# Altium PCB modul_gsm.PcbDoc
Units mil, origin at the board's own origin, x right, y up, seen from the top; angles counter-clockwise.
Board outline 2825 x 1976 mil, 2 copper layers (Top Layer, Bottom Layer); 39 components, 43 nets, 183 pads, 157 vias.
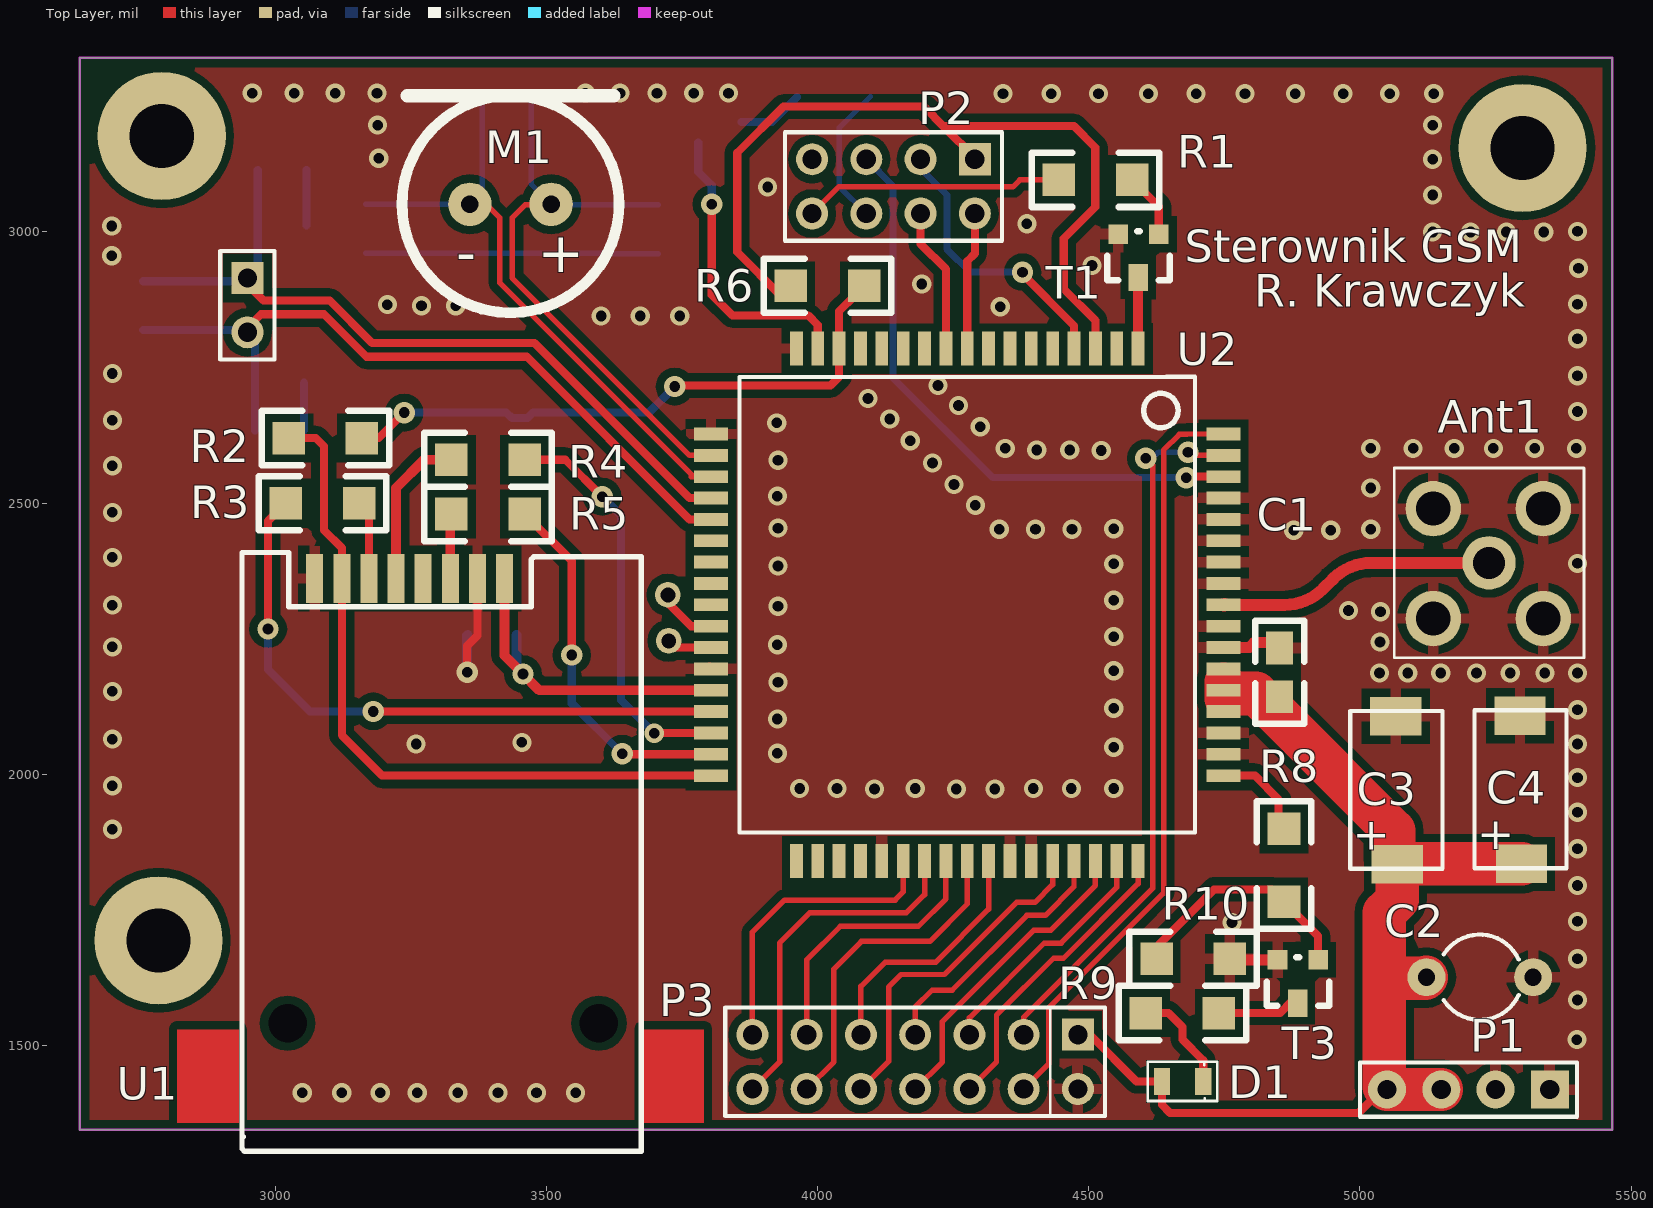
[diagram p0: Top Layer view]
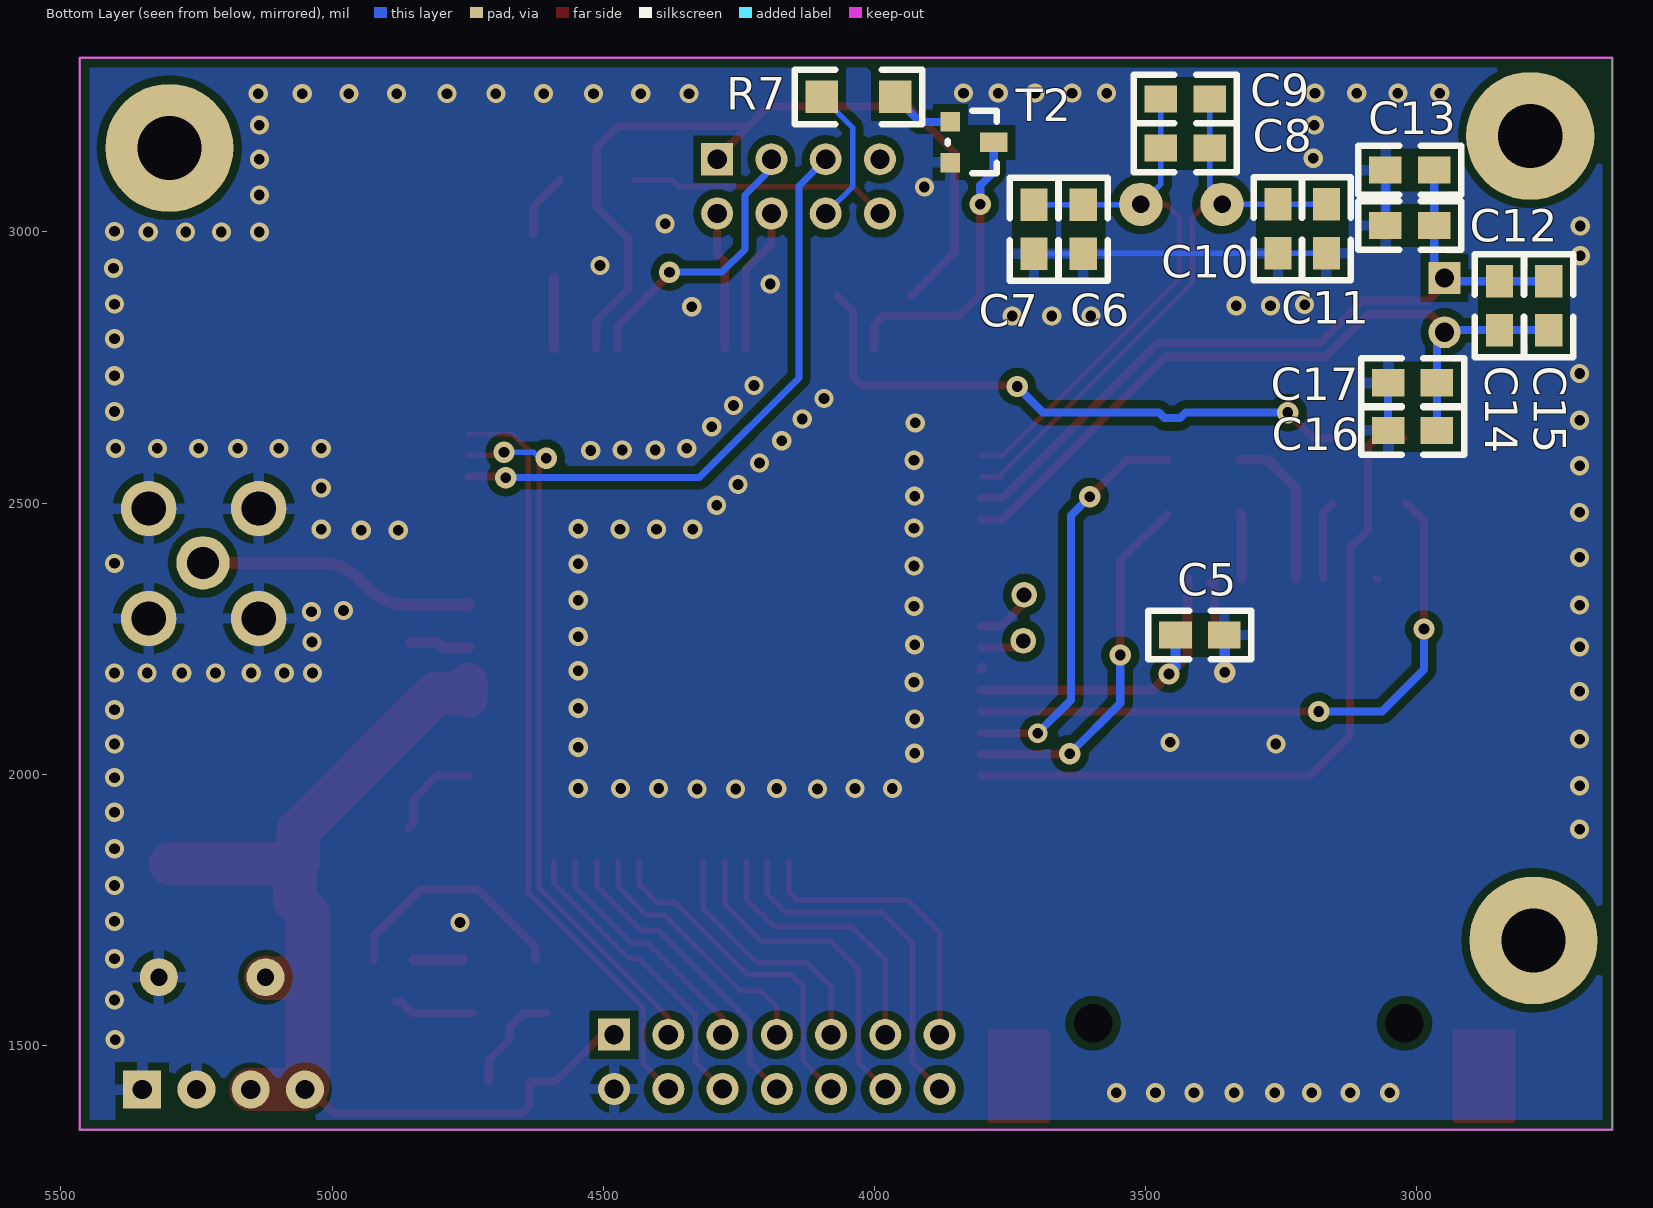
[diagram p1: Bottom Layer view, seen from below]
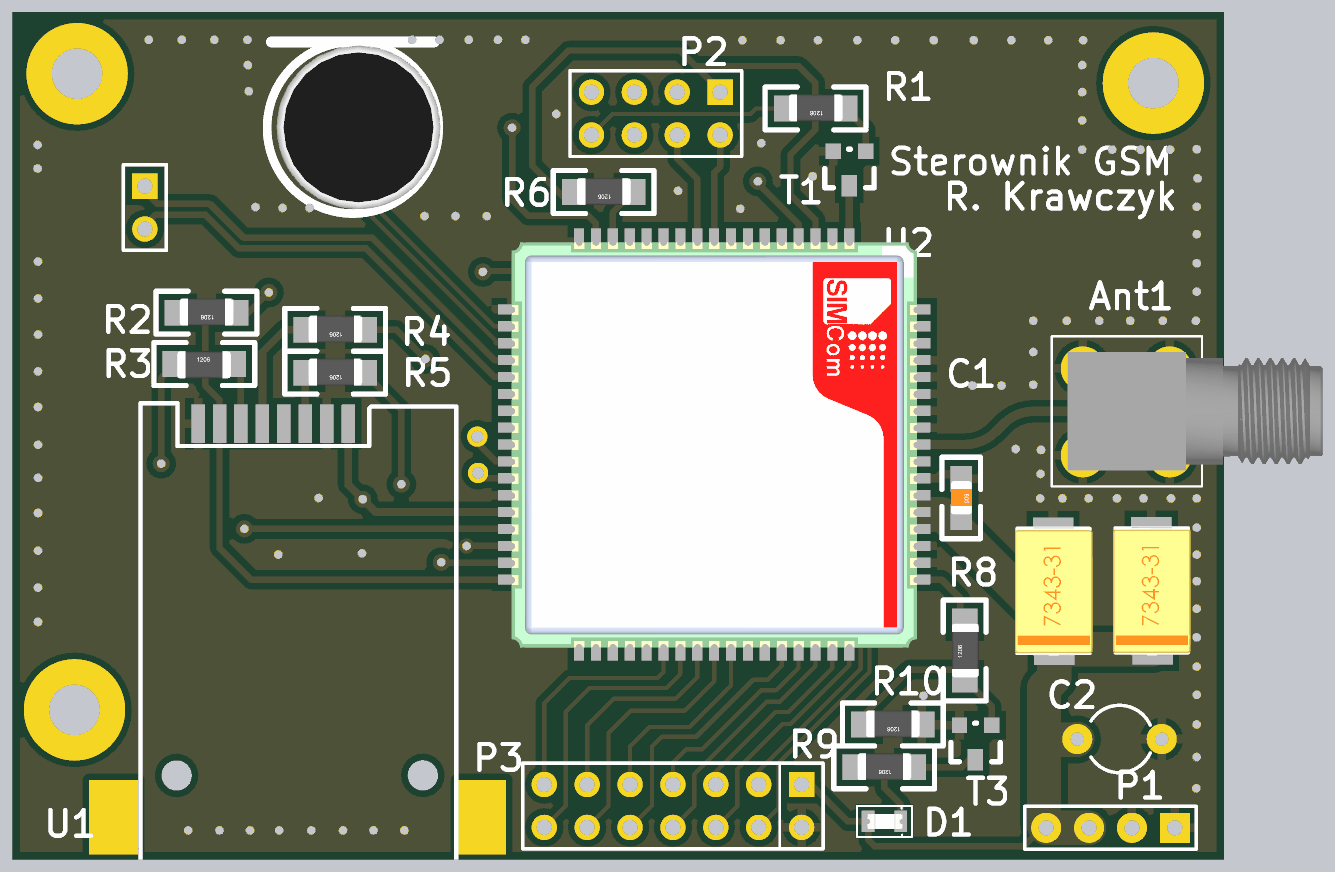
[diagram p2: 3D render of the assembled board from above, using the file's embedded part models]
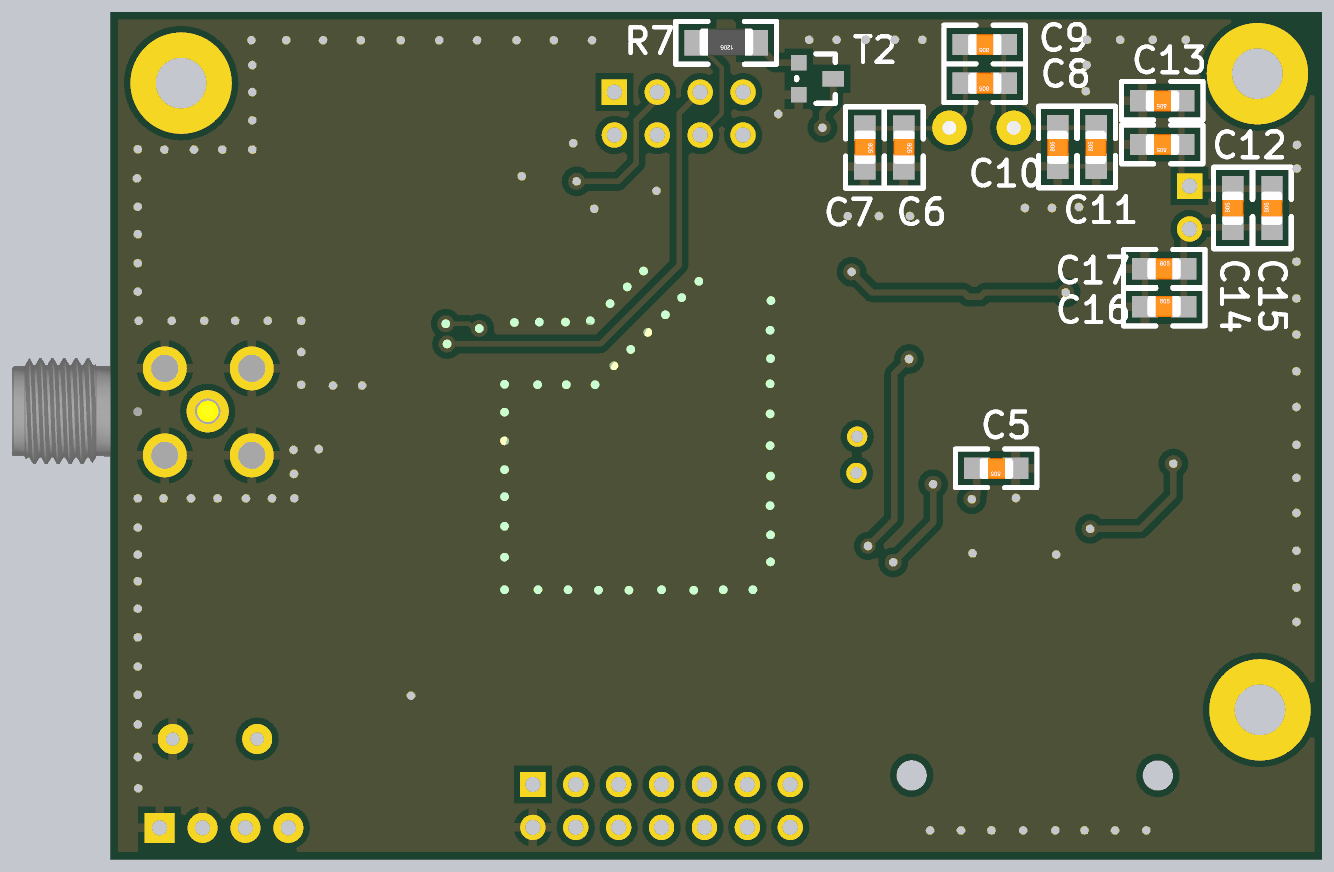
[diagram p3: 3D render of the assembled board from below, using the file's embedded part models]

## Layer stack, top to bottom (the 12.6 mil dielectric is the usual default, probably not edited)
Top Layer: signal copper 1.4
Dielectric: dielectric 12.6, FR-4, Dk 4.8
Bottom Layer: signal copper 1.4

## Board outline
2640,1345 2640,3321 5465,3321 5465,1345

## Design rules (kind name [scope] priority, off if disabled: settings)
Clearance Clearance_1 [All] p1: gap=15
Clearance [IsVia and InNet('GND')] p2: gap=0
DiffPairsRouting [All] p1: maxlimit=10 minlimit=10 mostfreqgap=10 maxuncoupledlength=500
PlaneConnect [All] p1: planeconnectstyle=Relief reliefexpansion=20 reliefentries=4 reliefconductorwidth=20 reliefairgap=10
PolygonConnect PolygonConnect_1 [(InNet('GND') AND IsVia)] p1: connectstyle=Direct reliefconductorwidth=10 reliefentries=4 polygonreliefangle="90 Angle"
PolygonConnect [All] p2: connectstyle=Relief reliefconductorwidth=20 reliefentries=4 polygonreliefangle="90 Angle"
RoutingVias [All] p1: holewidth=19.68 width=39.37 viastyle="Through Hole" minholewidth=19.68 minwidth=39.37 maxholewidth=19.68 maxwidth=39.37
SilkscreenOverComponentPads [All] p1: minsilkscreentomaskgap=10
SolderMaskExpansion [(IsVia)] p1: expansion=0
Width [All] p1: maxlimit=100 minlimit=10 preferedwidth=18 minimp=50.000000 maximp=50.000000 favimp=50.000000
25 further rules are at their usual default settings.

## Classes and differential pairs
differential pair MIC: +MIC_P -MIC_N
differential pair SPK: +SPK_P -SPK_N

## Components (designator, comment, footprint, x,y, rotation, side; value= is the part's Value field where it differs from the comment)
Ant1 "Antena" sma 5488,2290 r270 top
C1 "CAP" 0805 4852,2143 r90 top
C2 "CAP2" CAPR5-4X5 5221,1626 r0 top
C3 "CAP2" smd-d 5067,1971 r0 top
C4 "CAP2" smd-d 5296,1972 r0 top
C5 "CAP" 0805 3445,2257 r180 bottom
C6 "CAP" 0805 3615,2960 r90 bottom
C7 "CAP" 0805 3706,2960 r90 bottom
C8 "CAP" 0805 3472,3155 r180 bottom
C9 "CAP" 0805 3472,3245 r180 bottom
C10 "CAP" 0805 3256,3051 r270 bottom
C11 "CAP" 0805 3167,3051 r270 bottom
C12 "CAP" 0805 3058,3012 r180 bottom
C13 "CAP" 0805 3058,3114 r180 bottom
C14 "CAP" 0805 2848,2909 r270 bottom
C15 "CAP" 0805 2757,2909 r270 bottom
C16 "CAP" 0805 2963,2634 r0 bottom
C17 "CAP" 0805 2963,2722 r0 bottom
D1 "LED0" led_0805 4660,1440 r270 top
M1 "ELEKTRET" ELEKTRET 3509,3051 r0 top
P1 "Header 4" HDR1X4 5350,1419 r180 top
P2 "Header 4X2A" HDR2X4_CEN 4290,3134 r180 top
P3 "Header 7X2A" HDR2X7_CEN 4480,1520 r180 top
R1 "RES" 1206 4580,3096 r180 top
R2 "RES" 1206 3160,2620 r180 top
R3 "RES" 1206 3020,2500 r0 top
R4 "RES" 1206 3460,2580 r180 top
R5 "RES" 1206 3460,2480 r180 top
R6 "RES" 1206 4086,2901 r180 top
R7 "RES" 1206 3962,3249 r0 bottom
R8 "RES" 1206 4860,1765 r90 top
R9 "RES" 1206 4740,1560 r180 top
R10 "RES" 1206 4760,1660 r180 top
T1 "BC547B" "sot-23 rk" 4629,2996 r180 top
T2 "BC547B" "sot-23 rk" 3860,3203 r270 bottom
T3 "BC547B" "sot-23 rk" 4923,1658 r180 top
U1 "SIM" SIMCARD 3220,1800 r270 top
U2 "SIM900" SIM900 4591,2785 r270 top locked
? "GLOSNIK" hdr1x2 2949,2915 r270 top

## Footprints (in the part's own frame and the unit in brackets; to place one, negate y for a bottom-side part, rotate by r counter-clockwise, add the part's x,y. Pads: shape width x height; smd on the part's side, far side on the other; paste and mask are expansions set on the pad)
0805 [mil]
  rect 60x50 smd: 1(0,0) 2(90,0)
  silkscreen extent -50,-45 140,45, body extent 6,-25 85,24, height 31
1206 [mil]
  rect 60x60 smd: 1(0,0) 2(135,0)
  silkscreen extent -50,-50 185,50, body extent 4,-33 130,30, height 39
CAPR5-4X5 [mil] "Capacitor; 2 Leads"
  round 70 hole 31.5: 1(-98.43,0) 2(98.43,0)
  silkscreen extent -66,-79 72,79
ELEKTRET [mil]
  round 80 hole 32: 1(0,0) 2(-150,0)
  silkscreen extent -275,-200 125,200, body extent -253,-190 129,192, height 212
hdr1x2 [mm] "Connector; Header; 2 Position"
  rect 1.5x1.5 hole 0.9: 1(0,0)
  round 1.5 hole 0.9: 2(2.54,0)
  silkscreen extent -1.27,-1.27 3.81,1.27
HDR1X4 [mil] "Connector; Header; 4 Position"
  rect 70x70 hole 35.43: 1(0,0)
  round 70 hole 35.43: 2(100,0) 3(200,0) 4(300,0)
  silkscreen extent -50,-50 350,50
HDR2X4_CEN [mm] "Connector; Header; 4x2 Position"
  rect 1.5x1.5 hole 0.9: 1(0,0)
  round 1.5 hole 0.9: 2(2.54,0) 3(5.08,0) 4(7.62,0) 5(0,2.54) 6(2.54,2.54) 7(5.08,2.54) 8(7.62,2.54)
  silkscreen extent -1.27,-1.27 8.89,3.81
HDR2X7_CEN [mm] "Connector; Header; 7x2 Position"
  rect 1.5x1.5 hole 0.9: 1(0,0)
  round 1.5 hole 0.9: 2(2.54,0) 3(5.08,0) 4(7.62,0) 5(10.16,0) 6(12.7,0) 7(15.24,0) 8(0,2.54) 9(2.54,2.54) 10(5.08,2.54) 11(7.62,2.54) 12(10.16,2.54) 13(12.7,2.54) 14(15.24,2.54)
  silkscreen extent -1.27,-1.27 16.51,3.81
led_0805 [mil]
  rect 50x30 smd: 1(6,-25) 2(6,51)
  silkscreen extent -30,-51 42,77, body extent -12,-27 24,55, height 33
SIM900 [mm]
  rect 1.6x0.6 smd: 1(0,0) 2(0,-1) 3(0,-2) 4(0,-3) 5(0,-4) 6(0,-5) 7(0,-6) 8(0,-7) 9(0,-8) 10(0,-9) 11(0,-10) 12(0,-11) 13(0,-12) 14(0,-13) 15(0,-14) 16(0,-15) 17(0,-16) 35(24,-16) 36(24,-15) 37(24,-14) 38(24,-13) 39(24,-12) 40(24,-11) 41(24,-10) 42(24,-9) 43(24,-8) 44(24,-7) 45(24,-6) 46(24,-5) 47(24,-4) 48(24,-3) 49(24,-2) 50(24,-1) 51(24,0)
  rect 0.6x1.6 smd: 18(4,-20) 19(5,-20) 20(6,-20) 21(7,-20) 22(8,-20) 23(9,-20) 24(10,-20) 25(11,-20) 26(12,-20) 27(13,-20) 28(14,-20) 29(15,-20) 30(16,-20) 31(17,-20) 32(18,-20) 33(19,-20) 34(20,-20) 52(20,4) 53(19,4) 54(18,4) 55(17,4) 56(16,4) 57(15,4) 58(14,4) 59(13,4) 60(12,4) 61(11,4) 62(10,4) 63(9,4) 64(8,4) 65(7,4) 66(6,4) 67(5,4) 68(4,4)
  silkscreen extent 1.32,-18.67 22.67,2.67, body extent 0.03,-19.99 24.03,4.01, height 3.02
SIMCARD [mm]
  round 0 hole 1.8 unplated: 0(6.572,9.576) 0(6.577,-5.004)
  rect 2.3x0.8 smd: 1(-14.249,5.156) 2(-14.249,3.886) 3(-14.249,2.616) 4(-14.249,1.346) 5(-14.249,0.076) 6(-14.249,-1.194) 7(-14.249,-2.464) 8(-14.249,-3.734)
  Top Layer region: 6.856,11.608 11.25,11.608 11.25,14.503 6.856,14.503
  Top Layer region: 6.856,-10.185 11.25,-10.185 11.25,-7.29 6.856,-7.29
  silkscreen extent -15.47,-7.14 12.57,11.56, body extent -15.47,-7.24 12.62,11.53, height 1.1
sma [mm]
  round 2.5 hole 1.5: 1(-2.54,-6.35)
  round 2.6 hole 1.6: 2(-5.08,-3.81) 3(0.07,-3.81) 4(0.07,-8.96) 5(-5.08,-8.96)
  Top Layer lines w0.127: 0.051,-3.835 0.051,-3.81 ; -5.105,-3.81 -5.105,-3.759
  silkscreen extent -6.98,-10.8 1.91,-1.9, body extent -6.04,-9.86 0.96,5.24, height 9.86
smd-d [mil]
  rect 94.49x70.87 smd: 1(2,-137) 2(-1,136)
  silkscreen extent -85,-145 85,146, body extent -90,-151 91,148, height 122
"sot-23 rk" [mil]
  rect 35.98x35.98 smd: 1(75,0) 2(0,0)
  rect 35.98x50 smd: 3(37.99,80)
  silkscreen extent -20,-5 95,85

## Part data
C1 C5 C6 C7 C8 C9 C10 C11 C12 C13 C14 C15 C16 C17: "Condenstor"
C2 C3 C4: "kONDENSATOR ELEKTROLITYCZNY"
D1: "dioda elektroluminescencyjna LED"
M1: "Mikrofon"
P1: "Header, 4-Pin"
P2: "Header, 4-Pin, Dual row"
P3: "Header, 7-Pin, Dual row"
R1 R2 R3 R4 R5 R6 R7 R8 R9 R10: "Rezystor"
T1 T2 T3: "Tranzystor NPN"
U1: library part SIM_SLOT

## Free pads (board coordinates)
  round 47.24 hole 27.56: 0(3725.72,2246.28) 1(3724,2331)
  round 236.22 hole 118.11: 1(2785,1694) 1(2791,3177) 1(5300,3155)

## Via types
v1: diameter 35.43, hole 19.68, Top Layer to Bottom Layer, tented both sides, 143 vias
v2: diameter 39.37, hole 19.68, Top Layer to Bottom Layer, tented both sides, 14 vias

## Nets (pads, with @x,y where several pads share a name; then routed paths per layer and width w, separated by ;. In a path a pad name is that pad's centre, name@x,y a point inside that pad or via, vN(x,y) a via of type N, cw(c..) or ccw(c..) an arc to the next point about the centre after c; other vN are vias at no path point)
DTR: P2.1 R6.2 U2.3 | length 1526.8
  Top Layer w15: R6.2@3933,2882 3852,2963 3852,3146 3937,3231 4196,3231 4234.13,3192.87 ; P2.1 4290,3137 4234.13,3192.87 ; U2.3 4512.26,2836.74 4454,2895 4454,2988 4512,3046 4512,3156 4473,3195 4236.27,3195 4234.13,3192.87
GND: Ant1.2 Ant1.3 Ant1.4 Ant1.5 C1.2 C2.2 C3.2 C4.2 C5.2 C6.1 C7.1 C10.2 C11.2 C12.1 C13.1 C16.2 C17.2 P1.1 P1.2 P3.8 R10.1 T1.1 T2.1 T3.1 U1.2 U1.8 U2.17 U2.18 U2.29 U2.39 U2.45 U2.46 U2.53 U2.54 U2.58 U2.59 U2.61 U2.62 U2.63 U2.64 U2.65 | length 1193.8
  Top Layer w15: U1.8@3072,2360 U1.8 ; v2(3354,2188) 3354,2237 3373,2256 U1.2 U1.2@3380,2354
  Top Layer w18: U2.29@3801.05,2197 U2.29
  Top Layer w20: U2.58 4795.82,2233.82 4805,2243 C1.2@4855,2243 ; R10.1 4762,1658 T3.1
  Bottom Layer w10: C11.2 C10.2 3614,2961 C6.1 C7.1
  Bottom Layer w15: C16.2 C17.2 ; C12.1 C13.1
  Bottom Layer w18: v2(3354,2188) 3354,2256 C5.2
  other v1: 3050,1413 3123,1413 3194,1413 3262,1413 3337,1413 3411,1413 3482,1413 3554,1413 5400,1511 5401,1584 5401,1660 4764,1727 5401,1729 5401,1795 5401,1863 2700,1899 5401,1930 4105,1973 4256,1973 4327,1973 3967,1974 4036,1974 4180,1974 4398,1974 4468,1974 4546,1974 2700,1979 5401,1994 3926,2039 4546,2050 3260,2056 5401,2056 3455,2059 2700,2065 3926,2102 5401,2119 4546,2122 2700,2153 3927,2170 5036,2187 5088,2187 5149,2187 5215,2187 5277,2187 5341,2187 5401,2187 4546,2191 2700,2235 3926,2239 5037,2244 4546,2254 5038,2300 4979,2302 3927,2310 2700,2312 4546,2321 3927,2384 4546,2388 5401,2389 2700,2400 4878,2450 4946,2450 4335,2452 4402,2452 4469,2452 5020,2452 4546,2453 3927,2454 2700,2483 4291,2496 3926,2513 5020,2528 4251.76,2534.24 2700,2569 4212,2574 3927,2579 4523,2597 4404,2598 4465,2598 4346,2601 5020,2601 5098,2601 5174,2601 5246,2601 5322,2601 5399,2601 4171,2615 4300,2641 3925,2648 2700,2653 4133,2655 5401,2669 4260,2680 4093,2693 4222,2717 5401,2735 2700,2739 5401,2803 3601,2845 3673,2845 3746,2845 4337,2862 3270,2864 3333,2864 3207,2866 5401,2867 4192,2904 5403,2933 4506,2938 2699,2956 5134,3000 5204,3000 5270,3000 5339,3000 5401,3001 2699,3011 4386,3015 5134,3068 3908,3083 5134,3134 3191,3136 3189,3197 5134,3197 4342,3255 4431,3255 4518,3255 4610,3255 4698,3255 4788,3255 4881,3255 4969,3255 5055,3255 5136,3255 2958,3256 3035,3256 3111,3256 3188,3256 3572,3256 3636,3256 3704,3256 3772,3256 3836,3256
GPIO1: P3.7 U2.40 | length 554.7
  Top Layer w10: P3.7 3880,1709 3939.14,1768.14 4143,1768.14 4157.93,1783.07 U2.40
GPIO2: P3.14 U2.41 | length 655.8
  Top Layer w10: P3.14 3930,1470 3930,1689 3986,1745 4164,1745 4197.3,1778.3 U2.41
GPIO3: P3.6 U2.42 | length 510.8
  Top Layer w10: P3.6 3980,1658 4042,1720 4186,1720 4236.67,1770.67 U2.42
GPIO4: P3.13 U2.43 | length 616.6
  Top Layer w10: P3.13 4030,1470 4030,1641 4081,1692 4207,1692 4276.04,1761.04 U2.43
GPIO5: P3.5 U2.44 | length 472.1
  Top Layer w10: P3.5 4080,1609 4125,1654 4218,1654 4315.41,1751.41 U2.44
GPIO6: P3.12 U2.47 | length 633.3
  Top Layer w10: P3.12 4131,1471 4131,1608 4154,1631 4234,1631 4367,1764 4401,1764 4433.52,1796.52 U2.47
GPIO7: P3.4 U2.48 | length 483
  Top Layer w10: P3.4 4180,1571 4211,1602 4248,1602 4386,1740 4420,1740 4472.89,1792.89 U2.48
GPIO8: P3.11 U2.49 | length 575.9
  Top Layer w10: P3.11 4230,1470 4230,1544 4399,1713 4430,1713 4512.26,1795.26 U2.49
GPIO9: P3.3 U2.50 | length 450.8
  Top Layer w10: P3.3 4280,1551 4418,1689 4449,1689 4551.63,1791.63 U2.50
GPIO10: P3.10 U2.51 | length 559.8
  Top Layer w10: P3.10 4330,1470 4330,1556 4435,1661 4453.53,1661 4591,1798.47 U2.51
GPIO11: P3.2 U2.67 | length 1297.6
  Top Layer w10: P3.2 4380,1552 4618,1790 4618,2570 v2(4605,2583) ; v2@4688.85,2588.15 U2.67
  Bottom Layer w10: v2@4617,2582 4629,2594 v2(4683,2594)
GPIO12: P3.9 U2.68 | length 1407.6
  Top Layer w10: P3.9 4426,1466 4426,1569 4638,1781 4638,2598 4667,2627 4681,2627 4681.52,2627.52 U2.68
GSM_RST: P2.7 R7.2 | length 259.3
  Bottom Layer w10: P2.7 4040,3084 4040,3192 R7.2
GSM_RX: P2.6 U2.10 | length 268.3
  Top Layer w15: P2.6 4190,2978 4236.67,2931.33 U2.10
GSM_TX: P2.5 U2.9 | length 254.8
  Top Layer w15: U2.9 4276.04,2946.04 4290,2960 P2.5
MIC_N: C8.2 C9.2 C10.1 C11.1 M1.2 U2.20 | length 1121.2
  Top Layer w10: M1.2 3389.5,3051 3414.5,3026 3414.5,2905.83 3767,2553.33 3767,2548.78 U2.20
  Bottom Layer w10: C11.1 C10.1 M1.2 3382,3074 C8.2 C9.2
MIC_P: C6.2 C7.2 C8.1 C9.1 M1.1 U2.19 | length 1102
  Top Layer w10: M1.1@3508,3050 3461,3050 3437,3026 3437,2915.15 3764,2588.15 U2.19
  Top Layer w15: M1.1@3508,3050 M1.1
  Bottom Layer w10: C9.1 C8.1 3472,3088 M1.1 3510,3050 C6.2 C7.2
NetAnt1_1: Ant1.1 U2.60 | length 519.6
  Top Layer w22: U2.60@4749.92,2314 ccw(c4749.92,2312.56) U2.60 ; U2.60@4750.04,2311 cw(c4750.04,2312.56) U2.60 ; 4950,2359 ccw(c4948.3,2360.71) 4950.71,2360.71 ; Ant1.1 5021.42,2390 ccw(c5021.42,2290) 4950.71,2360.71 ; U2.60 4861.14,2312.56 ccw(c4861.14,2412.56) 4931.85,2341.85 4950.71,2360.71
NetD1_2: D1.2 R9.2 | length 194.5
  Top Layer w15: R9.2 4647,1560 4673,1534 4673,1511 4711,1473 D1.2
NetR1_1: R1.1 T1.2 | length 120.3
  Top Layer w15: R1.1 4629,3047 T1.2
NetR3_2: R3.2 U1.6 | length 146.5
  Top Layer w15: R3.2 3173,2482 U1.6
NetR4_2: R4.2 U1.5 | length 290.5
  Top Layer w18: U1.5 3223,2528 3275,2580 R4.2
NetR5_2: R5.2 U1.3 | length 119.8
  Top Layer w18: U1.3 3323,2478 R5.2
NetR7_1: R7.1 T2.2 | length 121.1
  Bottom Layer w15: T2.2 3916,3203 R7.1
NetR8_1: R8.1 R10.2 T3.2 | length 446.4
  Top Layer w10: T3.2@4921,1660 T3.2
  Top Layer w15: R10.2 4625,1682 4731,1788 4837,1788 R8.1 4923,1702 T3.2
NetR8_2: R8.2 U2.52 | length 177.7
  Top Layer w15: U2.52 4806.4,1997.6 4850,1954 4850,1910 R8.2
NetR9_1: R9.1 T3.3 | length 150.3
  Top Layer w15: R9.1 4853,1560 4873,1580 T3.3@4882.01,1580
NetT1_3: T1.3 U2.1 | length 131
  Top Layer w18: U2.1 T1.3
NetT2_3: T2.3 U2.16 | length 553.3
  Top Layer w15: v2(3805,3051) 3805,2884 3843,2846 3983,2846 4000.45,2828.55 U2.16
  Bottom Layer w15: T2.3 3780,3111 3805,3086 v2(3805,3051)
PWR: P2.8 R1.2 | length 480.7
  Top Layer w10: P2.8 4039,3083 4360,3083 4373,3096 R1.2
RI: P2.2 U2.4 | length 524.7
  Top Layer w15: v2(4378,2926) 4376,2924 4472.89,2827.11 U2.4
  Bottom Layer w13: P2.2 4190,3117 4239,3068 4239,3054.36 ; 4239.03,3054.34 4239.03,2967.97 4281,2926 v2(4378,2926)
SIM_CLK: R4.1 U2.32 | length 752.9
  Top Layer w15: R4.1 3535,2580 v2(3603,2512) ; v1@3697.66,2076.34 U2.32
  Bottom Layer w15: v2(3603,2512) 3638,2477 3638,2137 v1(3699,2076)
SIM_DAT: R3.1 U2.31 | length 1169.3
  Top Layer w15: v2(2987,2268) 2987,2467 R3.1 ; v2(3181,2116) 3181.29,2115.71 U2.31
  Bottom Layer w15: v2(2987,2268) 2987,2193 3064,2116 v2(3181,2116)
SIM_PRE: R2.2 U1.7 U2.34 | length 1329.3
  Top Layer w15: R2.2 3075,2620 3090,2605 3090,2450 3123,2417 U1.7 3123,2072 3197.4,1997.6 U2.34
SIM_RST: R5.1 U2.33 | length 682.6
  Top Layer w15: R5.1 3547,2393 v2(3547,2220) ; v2(3640,2037.94) 3639.03,2036.97 U2.33
  Bottom Layer w15: v2(3547,2220) 3547,2130.94 v2(3640,2037.94)
SIM_VDD: C5.1 U1.1 U2.30 | length 626
  Top Layer w18: U1.1 3423,2219 v2(3457,2185) 3486.92,2155.08 U2.30
  Bottom Layer w18: C5.1 3445,2197 v2(3457,2185)
SPK_N: ?.2 C14.2 C15.2 C16.1 C17.1 U2.22 | length 1407.9
  Top Layer w15: ?.2@2945,2819 2974.32,2848.32 3090.32,2848.32 3168.64,2770 3464.04,2770 3764,2470.04 U2.22
  Bottom Layer w15: C15.2 C14.2 2945,2819 ?.2 2963,2801 C17.1 C16.1
SPK_P: ?.1 C12.2 C13.2 C14.1 C15.1 U2.21 | length 1427.5
  Top Layer w15: ?.1@2943,2909 2978.68,2873.32 3100.68,2873.32 3179,2795 3478.41,2795 3764,2509.41 U2.21
  Bottom Layer w15: C15.1 C14.1 2943,2909 ?.1 2968,2934 C12.2 C13.2
STATUS: P2.3 U2.66 | length 1113.9
  Top Layer w13: v2@4678,2549 v2(4680,2547)
  Top Layer w15: v2@4678,2549 4748.26,2549 U2.66
  Bottom Layer w13: P2.3 4139.03,3084.97 4139.03,2730.97 4323,2547 v2(4680,2547)
VCC: C1.1 C2.1 C3.1 C4.1 D1.1 P1.3 P1.4 P3.1 U2.55 U2.56 U2.57 | length 2099.2
  Top Layer w15: P3.1 4502,1520 4588,1434 D1.1 4635,1391 4650,1376 4997,1376 P1.4@5045,1424 ; U2.55 4808,2115.71 ; C1.1@4838.71,2115.71 4840.5,2117.5 C1.1@4848,2125
  Top Layer w70: 4748.48,2139.15 U2.56@4748.48,2150 ; 4748.48,2171 U2.56 U2.56@4760.92,2155.08
  Top Layer w80: U2.56@4756.48,2150 U2.56@4766,2150 ; U2.56@4760.92,2155.08 U2.56@4766,2150 ; C2.1 5120.57,1624 5045,1624 ; P1.3 P1.4 5045,1424 5045,1624 ; C4.1 5070,1835 C3.1 ; U2.56@4766,2150 4808,2150 4840.5,2117.5 5062,1896 5062,1841 C3.1 ; 5045,1624 5045,1745 5069,1769 C3.1
VDD_EXT: R2.1 R6.1 U2.15 | length 1095.9
  Top Layer w15: R2.1 3191,2620 v2(3238,2667) ; v2(3737,2715) 3739,2717 4024,2717 4039.82,2732.82 U2.15 4039.82,2853.82 R6.1@4068,2882
  Bottom Layer w15: v2(3238,2667) 3426.2,2667 3436.41,2656.78 3465.59,2656.78 3475.8,2667 3689,2667 v2(3737,2715)
pads on no net: P2.4 U1.0 U1.4 U2.2 U2.5 U2.6 U2.7 U2.8 U2.11 U2.12 U2.13 U2.14 U2.23 U2.24 U2.25 U2.26 U2.27 U2.28 U2.35 U2.36 U2.37 U2.38
copper on no net: | length 199.2
  Top Layer w15: 3723,2249 3738.18,2233.82 3803.6,2233.82 ; 3724,2331 3724,2316 3766.81,2273.19 3803.6,2273.19

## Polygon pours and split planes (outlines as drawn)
GND on Top Layer "Bottom Layer-No Net" (solid, remove dead copper, pour order 1000): 2641,3319 5466,3319 5466,1343 2641,1343
GND on Bottom Layer "Bottom Layer-No Net" (solid, remove dead copper, pour order 1001): 2638.27,3322.18 5463.27,3322.18 5463.27,1346.18 2638.27,1346.18

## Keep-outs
Keep-Out Layer:
  lines w5: 3745,1345 5295,1345 ; 3755,1345 2640,1345 2640,3321 5465,3321 5465,1345 5239,1345

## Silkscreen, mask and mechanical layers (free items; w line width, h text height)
Top Overlay:
  lines w5: 4429,1370 4429,1570
  text "Sterownik GSM" at 4677,2944 h60
  text "R. Krawczyk" at 4805,2862 h60
Mechanical 1:
  lines w5: 4340,2444 4340,2446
